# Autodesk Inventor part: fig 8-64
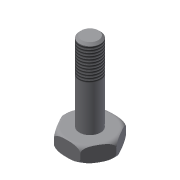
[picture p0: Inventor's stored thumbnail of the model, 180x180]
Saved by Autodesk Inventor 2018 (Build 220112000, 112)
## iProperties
Shininess: 77.0
Length Units: 11269
Angle Units: 11279
Time Units: 11290
Mass Units: 11283
Length Display Precision: 3
Angle Display Precision: 2
Created: 2002-01
Part Number: fig 8-64
Document SubType Name: Modeling
Designer: ***
Density: 1 g/cm^3
Material: Generic
Appearance: Default
Density: 0.0
Volumn: 0.0
Area: 0.0
PropertySet Name: Model Information
Control State: 0
Master: False
Checked Out: False
Author: ***
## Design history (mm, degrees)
sketch "Sketch1"
  geometry: C1 r 25 at (0, 0)
  constraints: 1 centre point
  dimensions: "d0" = 50 diameter of C1
extrude "Extrusion1" new body sketch "Sketch1" distance "d1" = 15; taper "d2" = 0 deg
fillet "Fillet1" dims "d3" = 5
sketch "Sketch2"
  geometry: L1 (25.058, 0)-(12.529, -21.701); L2 (12.529, -21.701)-(-12.529, -21.701); L3 (-12.529, -21.701)-(-25.058, 0); L4 (-25.058, 0)-(-12.529, 21.701); L5 (-12.529, 21.701)-(12.529, 21.701); L6 (12.529, 21.701)-(25.058, 0); 1 further point
  constraints: 12 end point, 11 other
extrude "Extrusion2" sketch "Sketch2" extent not by distance; stored distance "d4" = 15; taper "d5" = 0 deg
sketch "Sketch3"
  geometry: C1 r 10.044 at (0, 0); 1 further point
  constraints: 1 centre point, 1 coincident
extrude "Extrusion3" join sketch "Sketch3" distance "d6" = 75; taper "d7" = 0 deg
chamfer "Chamfer1" distance "d8" = 2; stored, may be unused: second distance "d9" = 2, angle "d16" = 45 deg
thread "Thread3" dims "d14" = 30, "d15" = 0
body "Solid1"
